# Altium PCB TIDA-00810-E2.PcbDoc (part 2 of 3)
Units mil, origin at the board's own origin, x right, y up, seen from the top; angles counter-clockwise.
Board outline 4527.56 x 3740.16 mil, 4 copper layers (Top Layer, Signal Layer 1, Signal Layer 2, Bottom Layer), stack 25.634 mil thick; 448 components, 198 nets, 1031 pads, 344 vias.
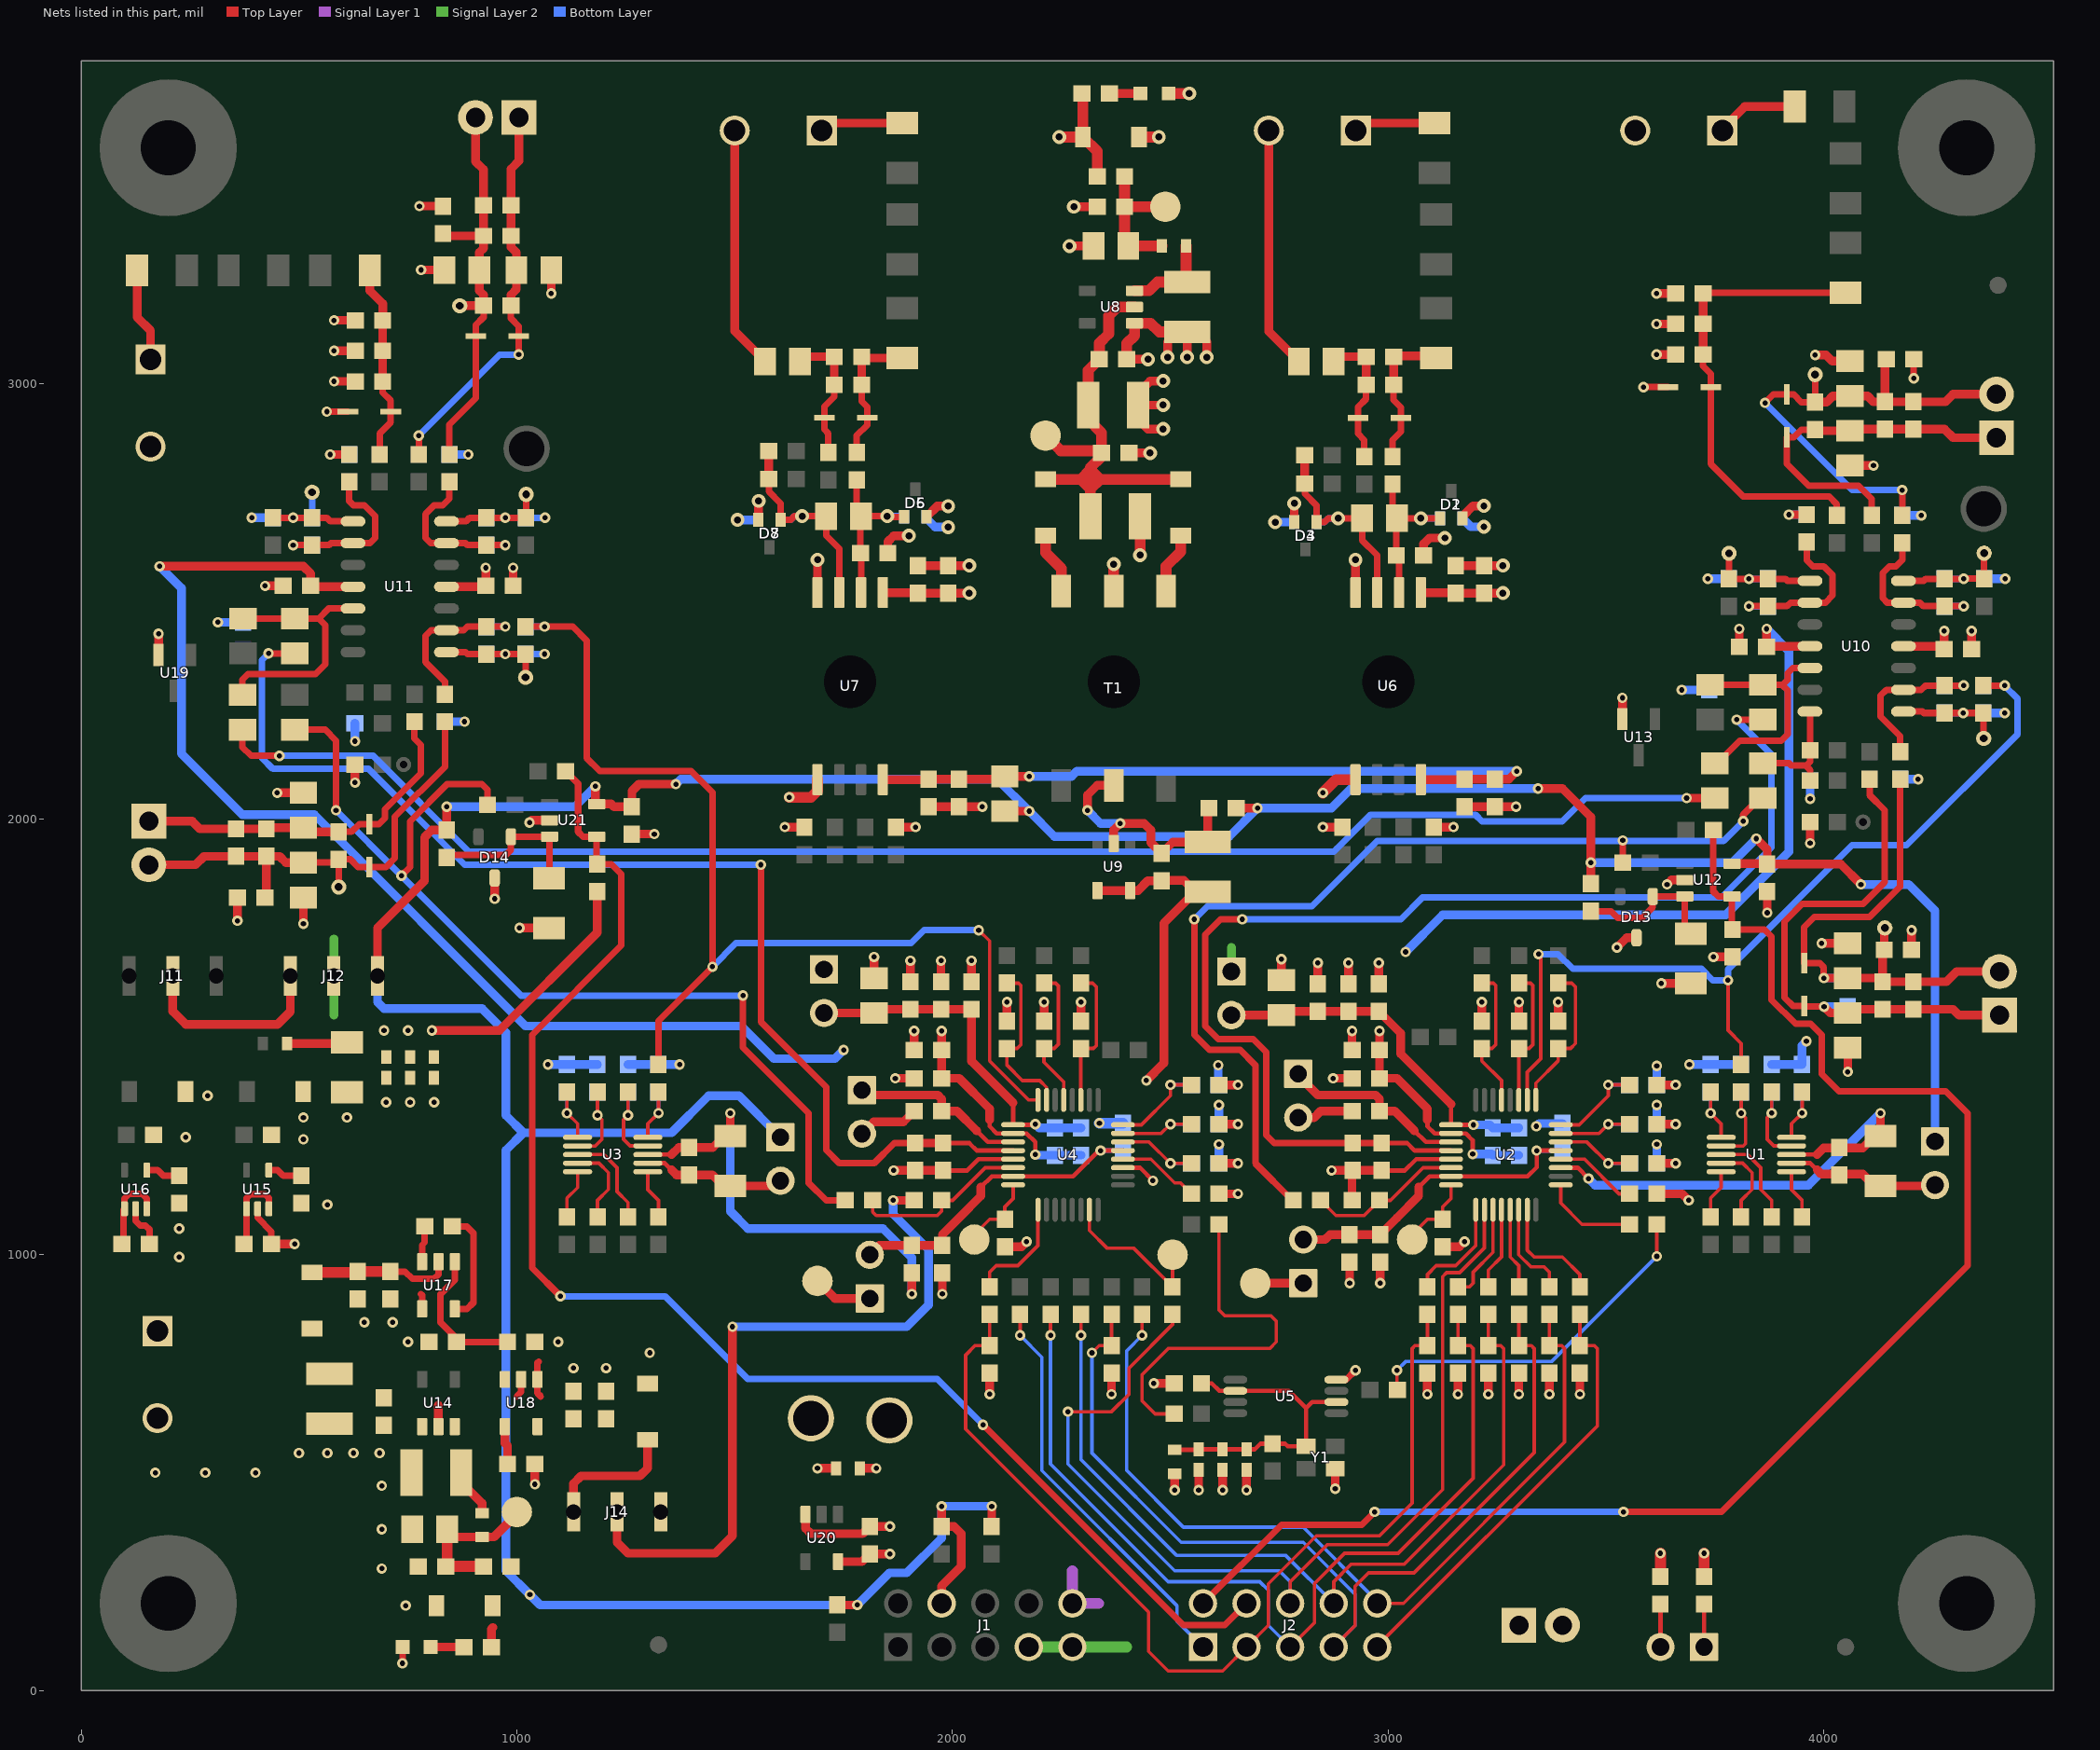
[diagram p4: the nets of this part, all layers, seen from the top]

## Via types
v1: diameter 24, hole 12, Top Layer to Bottom Layer, tented both sides, 309 vias
v2: diameter 32, hole 16, Top Layer to Bottom Layer, tented both sides, 35 vias

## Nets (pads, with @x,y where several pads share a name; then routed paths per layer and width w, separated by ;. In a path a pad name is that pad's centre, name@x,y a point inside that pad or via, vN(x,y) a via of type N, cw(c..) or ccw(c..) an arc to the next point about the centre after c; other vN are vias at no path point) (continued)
+5.0V_VDC: C35.1 C37.2 C40.1 C42.2 D1.2 D4.2 D5.2 D8.2 D10.1 R50.2 R65.2 R72.2 R73.2 U6.1 U7.1 | length 1014.1
  Top Layer w20: D8.2@1554.41,2686.5 1554.41,2729.41 v2(1555,2730) ; U7.1@1840,2519.57 1918.94,2519.57 C40.1@1920,2518.5 C42.2@1990,2518.5 v2(2038.5,2518.5) ; R65.2@1851.5,2610 1851.5,2636.5 1865,2650 v2(1900,2650) ; D5.2@1940.59,2693.5 1965,2717.91 v2(1990,2717.91) ; R73.2@2297.01,3665 R73.2@2299.04,3662.97 ; D4.2@2784.41,2681.5 v2(2784.41,2724.41) v2@2785,2725 ; U6.1@3075,2519.57 3153.94,2519.57 C37.2@3155,2518.5 C35.1@3220,2518.5 v2(3263.5,2518.5) ; R50.2@3081.5,2605 3081.5,2631.5 3095,2645 v2(3130,2645) ; D1.2@3170.27,2694.17 3194.68,2718.58 v2(3219.68,2718.58)
  Top Layer w25: v2(2245,3565) D10.1@2299.04,3565 ; R73.2@2299.04,3662.97 D10.1@2299.04,3565 ; R72.2@2332.01,3475 2332.01,3532.03 D10.1@2299.04,3565
+5V: C101.2 C115.2 D15.1 J1.4 J12.3 JP1.1 JP5.1 R122.2 R123.2 R134.2 R135.2 R140.2 R162.2 R163.2 R182.2 R183.2 U12.5 U21.5 | length 9121.8
  Top Layer w20: J12.3@680,1640 680,1750 788,1858 788,1958 804.54,1974.54 R123.2@839.13,1974.54 v1(839.13,2028.05) ; R135.2@941.5,100 941.5,141.5 945,145 ; v1(1180,2075) 1180,2037.72 U21.5@1183.27,2034.45 1216.73,2034.45 1222.64,2028.54 C115.2@1264.13,2028.54 1264.13,2064.13 1280,2080 v1(1365,2080) ; R140.2@1735,196.5 v1(1781.5,196.5) ; J1.4@1975,200 1975,240 2020,285 2020,360 2003.5,376.5 R163.2@1975,376.5 v1(1975,422.99) ; R162.2@2090,376.5 v1(2090,422.99) ; R183.2@2120,2018 v1(2176,2018) ; R182.2@2651.5,2025 v1(2700,2025) ; v1(3344,2070) 3400,2070 3465,2005 v1(3465,1900) R122.2@3465,1851.5 ; U12.5@3789.13,1897.4 3869.09,1897.4 C101.2@3870,1896.5 ; v1(3845,1955) 3870,1930 C101.2@3870,1896.5 ; v1(4085,1850) 4038.5,1896.5 C101.2@3870,1896.5
  Bottom Layer w20: J12.3@680,1640 680,1580 695,1565 920,1565 975,1510 975,1320 1015,1280 ; v1(839.13,2028.05) 1133.05,2028.05 v1(1180,2075) ; v1(1365,2080) 1376.5,2091.5 2102.5,2091.5 v1(2176,2018) 2234,1960 2635,1960 v1(2700,2025) 2870,2025 2915,2070 v1(3344,2070) ; JP5.1@1605,1270 1510,1365 1440,1365 1355,1280 1015,1280 ; v1(2090,422.99) v1(1975,422.99) 1975,350 1895,270 1855,270 v1(1781.5,196.5) 1053.5,196.5 v1(1030,220) 975,275 975,1240 1015,1280 ; v1(3465,1900) 3790,1900 v1(3845,1955) ; v1(4085,1850) 4195,1850 4255.13,1789.87 JP1.1@4255.13,1260
+6V_VDC: C50.1 C51.1 C52.2 C53.1 D9.1 D12.1 TP10.1 U8.2 | length 1150.1
  Top Layer w20: C52.2@2311.42,2917.09 C52.2@2311.42,2950 ; 2316.33,2801.47 2316.5,2801.47 ; 2316.42,2776.56 2316.5,2776.64 ; C51.1@2337.01,2845 C51.1@2342.01,2840
  Top Layer w25: D9.1@2213.5,2779.47 2313.5,2779.47 D12.1@2523.5,2779.47 ; TP10.1@2213.5,2880 2248.5,2845 C51.1@2337.01,2845 ; C52.2@2311.42,2917.09 2342.01,2886.5 C51.1@2342.01,2840 2342.01,2832.01 2316.5,2806.5 2316.5,2776.64 ; C52.2@2311.42,2950 2311.42,3029.41 C53.1@2337.01,3055 2337.01,3092.01 2358.5,3113.5 2358.5,3155 2378.5,3175 U8.2@2417.64,3175 ; 2316.33,2801.47 2294.33,2779.47 2316.42,2757.38 2338.5,2779.47 2316.5,2801.47 ; C50.1@2316.42,2695 2316.42,2776.56
-2P5V: C98.1 C99.1 D19.2 J14.1 U18.5 | length 315
  Top Layer w20: J14.1@1130,410 1130,475 1147.5,492.5 1282.5,492.5 1300,510 D19.2@1300,575.53
ADC1_CLKIN: R21.2 R47.1 | length 824
  Top Layer w8: v1(3020,735) 3020,691.5 R47.1@3021.5,690 ; v1(3616.56,996.56) R21.2@3616.56,1070
  Bottom Layer w8: v1(3020,735) 3040,755 3375,755 v1(3616.56,996.56)
ADC1_COMP: J2.2 R119.1 R124.1 U12.4 | length 3543.4
  Top Layer w15: J2.2@2575,200 2755,380 2939,380 v1@2968,409 ; v1(3540,410) 3765,410 4330,975 4330,1325 4280,1375 4035,1375 3995,1415 3995,1505 3970,1530 3935,1530 3880,1585 3880,1730 3863.5,1746.5 R124.1@3790,1746.5 3789.13,1747.36 U12.4@3789.13,1822.6 3757.4,1822.6 3746.5,1833.5 R119.1@3746.5,1975
  Bottom Layer w15: v1@2968,409 v1(2969,410) v1(3540,410)
ADC1_CS#: J2.9 R15.1 R164.1 | length 1008.9
  Top Layer w8: J2.9@2975,100 2975,102 3480,607 3480,785 3473.5,791.5 R164.1@3440,791.5 R164.1@3440,791.5 R15.1@3440.07,863.5
ADC1_REFOUT: C7.2 C8.2 R151.1 U2.12 | length 2772.8
  Top Layer w10: C8.2@2983.57,1256.49 3043.57,1256.49 3060.88,1239.19 U2.12@3144.08,1239.19
  Top Layer w15: v1(2665,1770) 2615,1770 2580,1735 2580,1525 2610,1495 2690,1495 2720,1465 2720,1275 2738.51,1256.49 C7.2@2918.57,1256.49 C8.2@2983.57,1256.49 ; v1(3800,2228.07) R151.1@3860,2228.07
  Bottom Layer w15: v1(2665,1770) 3029,1770 3079,1820 3765,1820 3880,1935 3880,2148.07 v1(3800,2228.07)
ADC1_SEL: JP9.1 R45.2 | length 98.5
  Top Layer w10: JP9.1@3725,100 R45.2@3725,198.5
ADC1_SPI_DONE: J2.6 R38.1 U2.18 | length 2360.4
  Top Layer w8: v1(2265,640) 2365,640 2405,680 2405,740 2505.07,840.07 R38.1@2505.07,863.5 ; J2.6@2775,200 2775,250 2860,335 2999,335 3125,461 3125,808 3125.07,950 3134.07,959 3164.07,959 3220.85,1015.79 U2.18@3220.85,1103.36
  Bottom Layer w8: v1(2265,640) 2265,520 2510,275 2750,275 2775,250 J2.6@2775,200
ADC2_CLKIN: R44.2 R48.1 | length 871.5
  Top Layer w8: R48.1@2508.5,635 2465,635 2435,665 2435,725 2495,785 2728,785 2743,800 2743,848 2731,860 2625,860 2611.56,873.44 R44.2@2611.56,1070
ADC2_COMP: J2.4 R120.2 R125.1 U21.4 | length 3316.6
  Top Layer w15: v1(1100,905) 1035,970 1035,1505 1240,1710 1240,1874 1217.46,1896.54 R125.1@1184.13,1896.54 1183.27,1897.41 U21.4@1183.27,1959.65 1151.54,1959.65 1140.63,1970.55 1140.63,2080.87 R120.2@1111.5,2110 ; v1(2070,610) 2530,150 2625,150 J2.4@2675,200
  Bottom Layer w15: v1(1100,905) 1340,905 1530,715 1965,715 v1(2070,610)
ADC2_REFOUT: C26.2 C27.2 R154.1 U4.12 | length 2737.8
  Top Layer w10: C27.2@1978.57,1256.49 2038.57,1256.49 2055.88,1239.19 U4.12@2139.08,1239.19
  Top Layer w15: v1(430,2380) R154.1@490,2380 ; v1(1560,1895) 1560,1535 1710,1385 1710,1240 1740,1210 1820,1210 1866.5,1256.49 C26.2@1913.57,1256.49
  Top Layer w20: C26.2@1913.57,1256.49 C27.2@1978.57,1256.49
  Bottom Layer w15: v1(430,2380) 415,2365 415,2140 440,2115 660,2115 880,1895 v1(1560,1895)
ADC2_SEL: JP9.2 R46.2 | length 98.5
  Top Layer w10: JP9.2@3625,100 R46.2@3625,198.5
ADC2_SPI_DONE: J2.1 R43.1 | length 937.5
  Top Layer w8: v1(2155,815) v1(2155,815) R43.1@2155.07,863.5
  Bottom Layer w8: v1(2155,815) 2205,765 2205,505 2515,195 2515,160 J2.1@2575,100
ADC_RESET: J2.3 R12.1 R14.1 R35.1 R37.1 | length 2293.4
  Top Layer w8: R37.1@2085.07,863.5 R35.1@2085,791.5 R35.1@2085,791.5 2051.5,791.5 2030,770 2030,600 2450,180 2450,90 2495,45 2620,45 J2.3@2675,100 2725,150 2725,245 2835,355 2980,355 3055,430 3055,785 3061.5,791.5 R12.1@3090,791.5 R12.1@3090,791.5 R14.1@3090.07,863.5
ADC_SPI_DRDY: J2.5 R19.1 R42.1 R167.1 | length 2155.2
  Top Layer w8: v1(2225,815) R42.1@2225.07,863.5 ; J2.5@2775,100 2830.65,155.65 2830.65,245.65 2900,315 3023,315 3195,487 3195,785 3188.5,791.5 R167.1@3160,791.5 R167.1@3160,791.5 R19.1@3160.07,863.5
  Bottom Layer w8: v1(2225,815) 2225,520 2495,250 2705.32,250 2725,230.32 2725,150 J2.5@2775,100
ADC_SPI_MISO: J2.7 R13.1 R18.1 R36.1 R41.1 | length 2279.6
  Top Layer w8: v1(2320,775) 2336.5,791.5 R36.1@2365,791.5 R36.1@2365,791.5 R41.1@2365.07,863.5 ; J2.7@2875,100 2924,149 2924,239 2955,270 3059,270 3335,546 3335,785 3328.5,791.5 R13.1@3300,791.5 R13.1@3300,791.5 R18.1@3300.07,863.5
  Bottom Layer w8: v1(2320,775) 2320,545 2525,340 2805,340 2924,221 2924,149 J2.7@2875,100
ADC_SPI_MOSI: J2.8 R17.1 R40.1 R165.1 | length 1977.9
  Top Layer w8: v1(2295,815) R40.1@2295.07,863.5 ; J2.8@2875,200 2875,250 2915,290 3037,290 3265,518 3265,785 3258.5,791.5 R165.1@3230,791.5 R165.1@3230,791.5 R17.1@3230.07,863.5
  Bottom Layer w8: v1(2295,815) 2295,530 2515,310 2765,310 J2.8@2875,200
ADC_SPI_SCLK: J2.10 R16.1 R39.1 R166.1 | length 1985.2
  Top Layer w8: v1(2435,815) R39.1@2435.07,863.5 ; J2.10@2975,200 3035,200 3405,570 3405,785 3398.5,791.5 R166.1@3370,791.5 R166.1@3370,791.5 R16.1@3370.07,863.5
  Bottom Layer w8: v1(2435,815) 2400,780 2400,505 2530,375 2805,375 2975,205 J2.10@2975,200
AGND: C3.2 C4.2 C9.2 C10.2 C11.2 C12.2 C15.2 C20.2 C21.2 C22.2 C23.2 C24.2 C25.2 C30.2 C36.1 C38.2 C41.1 C43.2 C56.1 C57.2 C58.2 C59.1 C60.1 C61.1 C64.1 C67.2 C68.2 C69.1 C74.2 C75.2 C76.1 C77.1 C78.1 C79.2 C80.1 C81.2 C82.2 C83.2 C84.2 C85.1 C86.2 C87.2 C88.2 C89.2 C90.2 C91.2 C92.2 C94.2 C95.2 C96.2 C97.2 C98.2 C99.2 C100.2 C101.1 C102.2 C103.2 C104.2 C107.2 C108.2 C109.2 C110.2 C111.2 C112.2 C113.2 C115.1 C122.2 C123.2 C124.1 C125.1 C126.2 C127.2 C128.1 C129.1 C130.2 C131.2 C132.2 C133.2 C134.2 C135.2 C136.2 C137.2 D13.3 D14.3 D15.2 D16.1 D17.2 D18.2 D19.1 D23.2 D24.2 J5.2 J6.2 J13.2 J14.3 L1.1 R9.1 R10.1 R11.1 R32.1 R33.1 R34.1 R45.1 R46.1 R79.2 R82.2 R88.1 R89.1 R90.1 R91.1 R118.2 R121.2 R132.1 R133.1 R141.2 R142.2 R170.2 R171.2 R174.1 R175.1 R176.1 R177.1 R178.1 R179.1 TP5.1 U6.5 U7.5 U12.2 U13.2 U14.1 U15.2 U16.2 U17.4 U18.1 U19.2 U21.2 | length 5444.6
  Top Layer w15: U16.2@125,1105.71 125,1078 135.5,1067.5 147.5,1067.5 156.5,1058.5 C90.2@156.5,1025 ; U15.2@405,1105.71 405,1085 436.5,1053.5 C87.2@436.5,1025 ; v1(563.63,2934.86) D24.2@612.13,2934.86 ; v1(737.52,62.52) D16.1@737.52,100 ; 780,910 782.6,907.4 U17.4@782.6,875.87 ; 1050,755 1047.4,752.4 U18.1@1047.4,714.13 1047.4,682.6 1055,675 ; v1(3586.07,2991.07) D23.2@3641.97,2991.07 ; v1(4206.5,3011.5) R170.2@4206.5,3055
  Top Layer w20: U19.2@177.6,2376.34 v1(177.6,2425) ; v1(358.5,1766.5) R142.2@358.5,1820 ; v1(422.01,2535) C69.1@463.5,2535 ; C87.2@436.5,1025 v1(490,1025) ; v1(450,2060) C125.1@510,2060 ; v1(510,1760) C123.2@510,1820 ; v1(571.5,2836.5) R82.2@615,2836.5 ; v1(580.37,3004.39) C61.1@628.88,3004.39 ; v1(580.37,3074.39) R91.1@628.88,3074.39 ; v1(580.37,3144.39) R90.1@628.88,3144.39 ; v1(628.5,2083.5) R121.2@628.5,2125 ; v1(776.5,3406.5) R171.2@830,3406.5 ; v1(780,3260) C127.2@834,3260 ; v1(949.13,1817.05) D14.3@949.13,1864.8 ; C64.1@991.5,2535 v1(991.5,2576.5) ; v1(1006.22,1749.96) R133.1@1074.13,1749.96 ; v1(1029.13,1992.05) 1034.13,1997.05 U21.2@1075,1997.05 ; v1(1041.5,473.5) C100.2@1041.5,520 ; v1(1079,3206) C129.1@1079,3260 ; C115.1@1264.13,1965.55 v1(1315.63,1965.55) ; v1(1615,1981.5) C112.2@1660,1981.5 ; v1(1690,510) L1.1@1732.44,510 ; C21.2@1820.07,1635 v1(1820.07,1683.5) ; v1(1868.57,1405) C24.2@1912.07,1405 ; C113.2@1870,1981.5 v1(1915,1981.5) ; C23.2@1903.57,1626.49 v1(1903.57,1675) ; C25.2@1912.07,1470 v1(1912.07,1513.5) ; C41.1@1945,2028.5 C43.2@2015,2028.5 v1(2068.5,2028.5) ; C20.2@1973.57,1626.49 v1(1973.57,1675) ; C22.2@2043.57,1626.49 v1(2043.57,1675) ; C109.2@2125.07,1536.49 v1(2125.07,1580) ; C108.2@2210.07,1536.49 v1(2210.07,1580) ; C107.2@2295.07,1536.49 v1(2295.07,1580) ; C30.2@2611.56,1140 v1(2655.07,1140) ; C4.2@2755.07,1630 v1(2755.07,1678.5) ; C10.2@2838.57,1621.49 v1(2838.57,1670) ; v1(2850,1981.5) C110.2@2895,1981.5 ; v1(2873.57,1405) C11.2@2917.07,1405 ; C3.2@2908.57,1621.49 v1(2908.57,1670) ; C12.2@2917.07,1470 v1(2917.07,1513.5) ; C9.2@2978.57,1621.49 v1(2978.57,1670) ; C111.2@3105,1981.5 v1(3150,1981.5) ; C38.2@3175,2028.5 C36.1@3245,2028.5 v1(3293.5,2028.5) ; C104.2@3215.07,1536.49 v1(3215.07,1580) ; C103.2@3300.07,1536.49 v1(3300.07,1580) ; C102.2@3390.07,1536.49 v1(3390.07,1580) ; v1(3525,1705) 3547.76,1727.76 D13.3@3570,1727.76 ; U13.2@3537.6,2229.41 v1(3537.6,2278.07) ; v1(3616.07,3066.07) C60.1@3659.69,3066.07 ; v1(3616.07,3136.07) R89.1@3659.69,3136.07 ; v1(3616.07,3206.07) R88.1@3659.69,3206.07 ; C15.2@3616.56,1140 3675,1140 v1(3690,1125) ; v1(3627.09,1622.91) R132.1@3695,1622.91 ; v1(3640,1850) 3650,1860 U12.2@3680.87,1860 ; C59.1@3805.8,2394.78 v1(3805.8,2436.28) ; v1(3870,1785) C101.1@3870,1833.5 ; v1(3920,2698.5) R79.2@3961,2698.5 ; v1(3968.5,1944.57) R118.2@3968.5,1993.07 ; v1(3980,3065) 4005,3065 4019,3051 C126.2@4060,3051 ; v1(3995,1715) C122.2@4055,1715 ; v1(4055,1420) C124.1@4055,1475 ; C128.1@4060,2811 v1(4114,2811) ; R141.2@4201.5,1700 v1(4201.5,1745) ; C56.1@4339.36,2390 v1(4339.36,2431.5)
  Top Layer w25: v1(1625,2050) 1675,2050 1690,2065 U7.5@1690,2090.43 ; v1(2850,2060) 2880.43,2090.43 U6.5@2925,2090.43 ; R46.1@3625,261.5 v1(3625,315) ; R45.1@3725,261.5 v1(3725,315)
  Bottom Layer w15: C68.2@1020,2378.5 v1(1063.5,2378.5) ; C75.2@1021.32,2691.5 v1(1064.82,2691.5)
  Bottom Layer w20: v1(391.5,2691.5) C58.2@440,2691.5 ; v1(571.5,2836.5) R179.1@615,2836.5 ; v1(628.5,2178.5) C77.1@628.5,2220 ; R175.1@835,2223.5 v1(880,2223.5) ; R177.1@845,2836.5 v1(888.5,2836.5) ; v1(1071.5,1436.5) C136.2@1115,1436.5 C137.2@1185,1436.5 ; C134.2@1255,1436.5 C135.2@1325,1436.5 v1(1373.5,1436.5) ; v1(2610,1435) 2610,1391.56 R34.1@2611.56,1390 ; R32.1@2611.56,1210 v1(2611.56,1253.5) ; R33.1@2611.56,1300 v1(2611.56,1343.5) ; R9.1@3616.56,1210 v1(3616.56,1253.5) ; R10.1@3616.56,1300 v1(3616.56,1343.5) ; R11.1@3616.56,1390 v1(3616.56,1433.5) ; v1(3691.5,1436.5) C132.2@3740,1436.5 C133.2@3810,1436.5 ; v1(3733.8,2551.28) C57.2@3782.3,2551.28 ; C130.2@3880,1436.5 C131.2@3950,1436.5 3950,1480 v1(3960,1490) ; v1(3920,2698.5) R178.1@3961,2698.5 ; v1(3968.5,2046.58) C76.1@3968.5,2088.07 ; R174.1@4175,2091.58 v1(4216.5,2091.58) ; R176.1@4180,2696.5 v1(4223.5,2696.5) ; C67.2@4366.41,2243.29 v1(4414.91,2243.29) ; C74.2@4367.87,2551.5 v1(4416.37,2551.5)
  other v1: 745,195 690,280 690,370 690,470 170,500 285,500 400,500 500,545 565,545 625,545 685,545 1130,740 1205,740 1305,775 750,800 1095,800 650,845 715,845 225,995 225,1060 565,1115 510,1265 240,1270 510,1315 610,1315 700,1350 755,1350 810,1350 290,1365
AVCC_3.3: C81.1 C82.1 C83.1 C84.1 C114.1 J1.7 J1.9 J15.1 JP3.1 JP7.1 L2.1 L5.2 R5.2 R6.2 R7.2 R8.1 R12.2 R13.2 R28.2 R29.2 R30.2 R31.1 R35.2 R36.2 R124.2 R125.2 R164.2 R165.2 R166.2 R167.2 TP1.1 TP6.1 U20.5 | length 2142.3
  Top Layer w20: L5.2@472.56,1485 607.91,1485 C81.1@610,1487.09 ; v1(805,1515) 960,1515 1184.13,1739.13 R125.2@1184.13,1833.55 ; TP6.1@1690,940 1730,900 JP7.1@1810,900 ; U20.5@1737.4,295.87 1792.36,295.87 C114.1@1810,313.5 v1(1856.5,313.5) ; v1(2085,680) R35.2@2085,728.5 ; R31.1@2120.07,1018.5 2158.57,1018.5 v1(2170.07,1030) ; v1(2365,680) R36.2@2365,728.5 ; v1(2510,460) L2.1@2510,497.44 ; R28.2@2611.56,1210 v1(2655.07,1210) ; R29.2@2611.56,1300 v1(2655.07,1300) ; R30.2@2611.56,1390 v1(2655.07,1390) ; TP1.1@2695,935 JP3.1@2805.07,935 ; v1(3090,680) R12.2@3090,728.5 ; R8.1@3125.07,1018.5 3163.57,1018.5 v1(3175.07,1030) ; v1(3160,680) R167.2@3160,728.5 ; v1(3230,680) R165.2@3230,728.5 ; v1(3300,680) R13.2@3300,728.5 ; v1(3370,680) R166.2@3370,728.5 ; v1(3440,680) R164.2@3440,728.5 ; R5.2@3616.56,1210 v1(3660.07,1210) ; R6.2@3616.56,1300 v1(3660.07,1300) ; R7.2@3616.56,1390 v1(3660.07,1390) ; v1(3746.5,1683.5) R124.2@3790,1683.5
  Signal Layer 2 w25: J1.7@2175,100 J1.9@2275,100 2400,100
  other v1: 695,1515 750,1515
AVDD: C56.2 C64.2 J12.2 JP2.1 JP6.1 R152.2 R155.2 U10.4 U11.4 | length 621.8
  Top Layer w20: U11.4@838.45,2533.03 926.53,2533.03 C64.2@928.5,2535 v1(928.5,2576.5) ; U10.4@4182.75,2396.56 4269.81,2396.56 C56.2@4276.37,2390 v1(4276.37,2431.5)
  Signal Layer 2 w20: 580,1550 J12.2@580,1640 580,1725 ; 2640,1705 2640.07,1704.93 JP2.1@2640.07,1650
  Bottom Layer w20: v1(313.5,2451.5) R155.2@371.46,2451.5 ; v1(3673.72,2296.28) R152.2@3737.3,2296.28
AVDD_J1: C3.1 C4.1 C9.1 C10.1 C118.1 C119.1 JP2.2 U2.9 | length 829.6
  Top Layer w10: 3144.08,1345.98 U2.9@3144.08,1298.24 v1(3195.76,1298.24)
  Top Layer w20: JP2.2@2640.07,1550 C4.1@2755.07,1550 2763.57,1558.5 C10.1@2838.57,1558.5 C3.1@2908.57,1558.5 C9.1@2978.57,1558.5 3028.57,1508.5 3028.57,1461.5 3144.08,1345.98
  Bottom Layer w20: v1(3195.76,1298.24) 3233.26,1298.24 C118.1@3240,1291.5 C119.1@3300,1291.5
AVDD_J2: C20.1 C21.1 C22.1 C23.1 C120.1 C121.1 JP6.2 U4.9 | length 807
  Top Layer w10: 2139.08,1349.02 U4.9@2139.08,1298.24 2188.24,1298.24 v1(2190,1300)
  Top Layer w20: JP6.2@1705.07,1555 C21.1@1820.07,1555 1828.57,1563.5 C23.1@1903.57,1563.5 C20.1@1973.57,1563.5 C22.1@2043.57,1563.5 2043.57,1444.53 2139.08,1349.02
  Bottom Layer w20: v1(2190,1300) 2198.5,1291.5 C120.1@2235,1291.5 C121.1@2295,1291.5
AVSS: C7.1 C8.1 C11.1 C12.1 C13.2 C14.2 C24.1 C25.1 C26.1 C27.1 C28.2 C29.2 C59.2 C69.2 C118.2 C119.2 C120.2 C121.2 J14.2 JP4.2 JP8.2 U2.10 U2.13 U4.10 U4.13 U10.11 U11.11 | length 8037.1
  Top Layer w10: C27.1@1978.57,1193.5 2033.57,1193.5 2059.57,1219.5 U4.13@2139.08,1219.5 ; 2085.07,1310 2085.07,1295 2101.51,1278.56 U4.10@2139.08,1278.56 2170.13,1278.56 2190,1258.68 v1(2190,1230) ; C8.1@2983.57,1193.5 3038.57,1193.5 3064.57,1219.5 U2.13@3144.08,1219.5 ; 3090.07,1310 3090.07,1295 3106.51,1278.56 U2.10@3144.08,1278.56 3178.24,1278.56 3194,1262.8 v1(3194,1231)
  Top Layer w20: v1(180,2580) 510,2580 526.5,2563.5 C69.2@526.5,2535 528.47,2533.03 U11.11@623.88,2533.03 ; J14.2@1230,410 1230,340 1255,315 1455,315 1495,355 v1(1495,835) ; JP8.2@1792,1278 1819,1305 1887.07,1305 C28.2@1912.07,1330 ; v1(1863.57,1125) C29.2@1912.07,1125 ; v1(1865.06,1193.5) C26.1@1913.57,1193.5 C27.1@1978.57,1193.5 ; v1(1975.06,1513.5) C25.1@1975.06,1470 C24.1@1975.06,1405 2015.07,1405 2085.07,1335 2085.07,1310 ; JP4.2@2793.57,1311.5 2790.07,1315 2830.07,1315 2845.07,1330 C13.2@2917.07,1330 ; v1(2870.06,1193.5) C7.1@2918.57,1193.5 ; C14.2@2917.07,1125 2917.07,1192.01 C7.1@2918.57,1193.5 ; v1(2980.06,1513.5) C12.1@2980.06,1470 C11.1@2980.06,1405 3020.07,1405 3090.07,1335 3090.07,1310 ; C8.1@2983.57,1193.5 C7.1@2918.57,1193.5 ; v1(3868.8,2436.28) C59.2@3868.8,2394.78 3870.57,2396.56 U10.11@3968.18,2396.56
  Bottom Layer w20: v1(180,2580) 230,2530 230,2150 370,2010 535,2010 1020,1525 1515,1525 1590,1450 1730,1450 v1(1750,1470) ; v1(1495,835) 1895,835 1945,885 1945,1012 1863.57,1093.43 v1(1863.57,1125) ; v1(2190,1230) 2191.5,1228.5 C120.2@2235,1228.5 C121.2@2295,1228.5 ; v1(3040,1695) 3125,1780 3775,1780 3920,1925 3920,2385.08 v1(3868.8,2436.28) ; v1(3194,1231) 3237.5,1231 C118.2@3240,1228.5 C119.2@3300,1228.5
CT_1_OUT: C67.1 R96.2 R143.2 U2.2 | length 2149.7
  Top Layer w8: U2.2@3319.28,1355.33 3319.28,1419.21 3350,1449.93 3350,1685 v1(3345,1690) ; v1(3780,1630) 3780,1515.13 3810.13,1485 R143.2@3810.13,1436.49
  Top Layer w15: R96.2@4366.41,2306.28 v1(4414.92,2306.28)
  Bottom Layer w15: v1(3345,1690) 3390,1690 3423.87,1656.13 3718.87,1656.13 3745,1630 v1(3780,1630) 3780,1655 4065,1940 4190,1940 4445,2195 4445,2276.19 v1(4414.92,2306.28) C67.1@4366.41,2306.28
CT_2_OUT: C68.1 R97.2 R149.2 U4.8 | length 2568.6
  Top Layer w8: v1(2060,1745) 2085,1720 2085,1445 2174.67,1355.33 U4.8@2196.17,1355.33
  Top Layer w15: R97.2@1020,2441.5 v1(1063.5,2441.5) 1128.5,2441.5 1160,2410 1160,2140 1190,2110 1400,2110 1449,2061 v1(1449,1661) 1325.07,1537.07 R149.2@1325.07,1436.49
  Bottom Layer w15: C68.1@1020,2441.5 v1(1063.5,2441.5) ; v1(1449,1661) 1503,1715 1905,1715 1935,1745 v1(2060,1745)
DC_IN: C85.2 C86.1 C87.1 C90.1 D20.2 J13.1 U14.2 U15.1 U15.3 U16.1 U16.3 | length 430.5
  Top Layer w15: C90.1@93.5,1025 97,1028.5 97,1103.3 U16.1@99.41,1105.71 99.41,1129.41 110,1140 140,1140 150.59,1129.41 U16.3@150.59,1105.71 ; C87.1@373.5,1025 379.41,1030.91 U15.1@379.41,1105.71 379.41,1130.41 388,1139 422,1139 430.59,1130.41 U15.3@430.59,1105.71
  Top Layer w20: U14.2@820,605.87 820,655
EXT_REF1: R20.1 R127.1 R157.1 | length 2261.2
  Top Layer w15: v1(2555,1770) 2555,1505 2590,1470 2660,1470 2695,1435 2695,1210 2780,1125 R157.1@2782.07,1125 ; R127.1@3538.5,1900 v1(3538.5,1951) ; v1(3815,1995) 3815,2010 3853.07,2048.07 R20.1@3860,2048.07
  Bottom Layer w15: v1(2555,1770) 2585,1800 2825,1800 2975,1950 3770,1950 v1(3815,1995)
EXT_REF2: R128.1 R139.1 R161.1 | length 2354.8
  Top Layer w15: R139.1@490,2205 560,2205 585,2180 v1(585,2020) ; v1(735,1870) 755,1890 755,1995 840,2080 920,2080 932.64,2067.36 R128.1@932.64,2032.05 ; v1(1519,1595) 1519,1476 1670,1325 1670,1165 1710,1125 R161.1@1753.57,1125
  Bottom Layer w15: v1(585,2020) v1(735,1870) 1010,1595 v1(1519,1595)
GND: C1.2 C2.2 C5.2 C6.2 C16.2 C17.2 C18.2 C19.2 C31.2 C32.2 C33.2 C34.2 C45.1 C46.1 C114.2 C116.2 C117.2 J1.10 J15.2 L1.2 TP3.1 U1.3 U2.27 U3.3 U4.27 U5.4 U9.4 U9.5 U20.3 Y1.2 | length 3956.6
  Top Layer w10: U3.3@1300.77,1230 1355.07,1230 ; U4.27@2391.05,1199.82 2430.19,1199.82 v1(2460,1170) ; U2.27@3396.05,1199.82 3435.19,1199.82 v1(3460,1175) ; U1.3@3930.13,1230 3984.42,1230
  Top Layer w15: U5.4@2903.39,713.39 v1(2925,735)
  Top Layer w20: 1355.07,1230 1371.56,1246.49 C16.2@1395.07,1246.49 1449.56,1246.49 1475.15,1272.09 C17.2@1490.07,1272.09 1490.07,1324.93 v1(1490,1325) ; U20.3@1662.6,404.13 1662.6,372.4 1675,360 1793.5,360 C114.2@1810,376.5 v1(1856.5,376.5) ; L1.2@1787.56,510 v1(1825,510) ; v1(1906.57,910) C19.2@1906.57,958.5 ; v1(1976.57,910) C18.2@1976.57,958.5 ; U9.4@2332.6,1835.87 U9.5@2407.4,1835.87 2425.87,1835.87 2448.5,1858.5 C46.1@2480,1858.5 2480.77,1859.27 2530.73,1859.27 C45.1@2557.09,1832.91 ; v1(2445,1400) 2485,1440 2485,1760.83 C45.1@2557.09,1832.91 ; v1(2462.13,705) C31.2@2508.5,705 ; v1(2565,460) C32.2@2565,506.38 ; C45.1@2578.09,1825 C45.1@2586,1832.91 C45.1@2557.09,1832.91 ; v1(2620,460) C33.2@2620,506.38 ; v1(2675,460) C34.2@2675,506.38 ; v1(2878.46,463.03) Y1.2@2878.46,509.41 ; v1(2911.57,935) C5.2@2911.57,983.5 ; v1(2981.57,935) C6.2@2981.57,983.5 ; 3984.42,1230 3999.42,1245 C1.2@4027.93,1245 ; C1.2@4034.42,1251.49 C1.2@4027.93,1245 ; C2.2@4129.42,1272.08 4116.51,1272.08 4089.42,1245 4036.63,1245 C1.2@4035.13,1246.49 4033.64,1245 C1.2@4027.93,1245 ; v1(4130,1325) 4130.13,1324.87 C2.2@4130.13,1272.08
  Signal Layer 1 w25: 2275,275 J1.10@2275,200 2335,200
  Bottom Layer w20: v1(1490,1325) 1490,1100 1530,1060 1840,1060 1906.57,993.43 v1(1906.57,910) ; v1(3340,1295) 3346.5,1301.5 C116.2@3400,1301.5 ; v1(3460,1175) 3475,1160 3965,1160 v1(4130,1325)
  Bottom Layer w25: v1(2337.18,1302.18) C117.2@2391.05,1302.18
GND_VDC: C35.2 C37.1 C40.2 C42.1 C47.1 C48.2 C49.1 C50.2 C51.2 C52.1 C53.2 D2.1 D3.1 D6.1 D7.1 D10.2 D11.1 J3.2 J4.2 R59.1 R70.1 T1.5 U6.4 U7.4 U8.1 | length 2850.4
  Top Layer w20: J4.2@1500,3580 1500,3120 R70.1@1570,3050 ; R70.1@1565,3045 R70.1@1570,3040 ; U7.4@1690,2519.57 v2(1690,2595) ; C40.2@1920,2581.5 C42.1@1990,2581.5 v2(2038.5,2581.5) ; v2(2268.5,3315) C47.1@2323.5,3315 ; v2(2278.5,3405) C48.2@2332.01,3405 ; C53.2@2400,3055 v2(2448.5,3055) ; C51.2@2405,2840 v2(2453.5,2840) ; 2448.77,2894.73 2448.5,2895 ; v2(2483.5,2895) 2448.5,2895 ; v2(2483.5,2950) C52.1@2425.59,2950 ; v2(2483.5,3005) 2453.5,3005 2425.59,2977.09 C52.1@2425.59,2950 ; v2(2493.5,3060) 2493.5,3095 2503.5,3105 2503.5,3117.91 C49.1@2538.5,3117.91 ; v2(2538.5,3060) C49.1@2538.5,3117.91 ; v2(2583.5,3060) 2583.5,3095 2560.59,3117.91 C49.1@2538.5,3117.91 ; J3.2@2725.96,3580 2725.96,3119.03 R59.1@2795,3050 ; U6.4@2925,2519.57 v2(2925,2595) ; C37.1@3155,2581.5 3230,2581.5 v2(3263.5,2581.49) ; C52.1@2425.59,2950 2425.59,2917.91 2448.5,2895
  Top Layer w25: T1.5@2370,2522.64 v2(2370,2585) ; C53.2@2400,3055 2400,3091.5 2417.64,3109.13 U8.1@2417.64,3137.6 2454.69,3137.6 2474.37,3117.91 C49.1@2503.5,3117.91 ; D10.2@2427.97,3565 v2(2473.5,3565) ; v2(2430.59,2605.59) C50.2@2430.59,2695 ; D11.1@2495.98,3665 v2(2543.5,3665)
  Bottom Layer w20: v2(1506.5,2686.5) D7.1@1554.41,2686.5 ; D6.1@1940.59,2693.5 1940.59,2689.41 1960,2670 v2(1990,2670) ; v2(2740.91,2680.9) 2741.5,2681.5 D3.1@2784.41,2681.5 ; D2.1@3170.27,2694.17 D2.1@3170.27,2690.08 3189.68,2670.67 v2(3219.68,2670.67)
NetC1_1: C1.1 C2.1 JP1.2 U1.2 | length 353.1
  Top Layer w10: U1.2@3930.13,1210.31 3969.11,1210.31 3984.42,1195
  Top Layer w20: 3984.42,1195 3994.42,1185 C1.1@4030.92,1185 ; C1.1@4034.42,1188.5 C1.1@4030.92,1185 ; JP1.2@4254.42,1160 4252.34,1157.91 4116.51,1157.91 4089.42,1185 4036.63,1185 C1.1@4035.13,1183.5 4033.64,1185 C1.1@4030.92,1185
NetC5_1: C5.1 C6.1 C116.1 JP3.2 U2.15 U2.29 | length 769.2
  Top Layer w10: 3070.07,1155 3095.07,1180 3143.95,1180 U2.15@3144.08,1180.13 3320.13,1180.13 3340.81,1200.81 v1(3340.81,1239.19) U2.29@3396.05,1239.19
  Top Layer w20: JP3.2@2805.07,1035 2855.07,1035 2866.56,1046.5 C5.1@2911.57,1046.5 C6.1@2981.57,1046.5 3020.07,1085 3070.07,1135 3070.07,1155
  Bottom Layer w10: v1(3340.81,1239.19) 3341.5,1238.5 C116.1@3400,1238.5
NetC13_1: C13.1 JP4.1 U2.11 | length 434.8
  Top Layer w10: 3060.07,1285 3086.19,1258.87 U2.11@3144.08,1258.87
  Top Layer w20: JP4.1@2790.07,1415 2838.49,1366.57 2970.99,1366.57 2980.06,1357.5 C13.1@2980.06,1330 3015.07,1330 3060.07,1285
NetC14_1: C14.1 R157.2 U2.14 | length 359
  Top Layer w8: R157.2@2845.06,1125 2880.06,1090 2945.06,1090 C14.1@2980.06,1125 3005.07,1125 3079.88,1199.82 U2.14@3144.08,1199.82
NetC15_1: C15.1 U2.28 | length 190.4
  Top Layer w8: U2.28@3396.05,1219.5 3450.5,1219.5 3530,1140 C15.1@3553.57,1140
NetC16_1: C16.1 C17.1 JP5.2 U3.2 | length 330.9
  Top Layer w10: U3.2@1300.77,1210.31 1339.75,1210.31 1355.07,1195
  Top Layer w20: 1355.07,1195 1366.56,1183.5 C16.1@1395.07,1183.5 1448.57,1183.5 1474.16,1157.91 C17.1@1490.07,1157.91 1592.91,1157.91 JP5.2@1605,1170
NetC18_1: C18.1 C19.1 C117.1 JP7.2 U4.15 U4.29 | length 731.4
  Top Layer w10: 2065.07,1155 2090.2,1180.13 U4.15@2139.08,1180.13 ; U4.15@2139.08,1180 2276.63,1180 2335.81,1239.19 v1(2340,1239.19) U4.29@2391.05,1239.19
  Top Layer w20: JP7.2@1831.5,1021.5 C19.1@1906.57,1021.5 C18.1@1976.57,1021.5 1976.57,1046.5 2015.07,1085 2065.07,1135 2065.07,1155
  Bottom Layer w10: v1@2335.81,1239.19 v1(2340,1239.19) C117.1@2391.05,1239.19
NetC28_1: C28.1 JP8.1 U4.11 | length 423.2
  Top Layer w10: 2055.07,1285 2081.19,1258.87 U4.11@2139.08,1258.87
  Top Layer w20: JP8.1@1785,1375 1785,1366.57 1965.99,1366.57 1975.06,1357.5 C28.1@1975.06,1330 2010.07,1330 2055.07,1285
NetC29_1: C29.1 R161.2 U4.14 | length 412.7
  Top Layer w8: R161.2@1816.56,1125 1816.56,1098.44 1825,1090 1965,1090 1975.06,1100.06 C29.1@1975.06,1125 2000.07,1125 2074.88,1199.82 U4.14@2139.08,1199.82
NetC30_1: C30.1 U4.28 | length 190.4
  Top Layer w8: U4.28@2391.05,1219.5 2455.57,1219.5 2510.07,1165 2523.57,1165 C30.1@2548.57,1140
NetC31_1: C31.1 C32.1 C33.1 C34.1 L2.2 R49.1 U5.2 U5.6 Y1.4 | length 736.4
  Top Layer w10: L2.2@2510,552.56 C32.1@2563.94,552.56 ; C32.1@2565,553.62 C33.1@2620,553.62 C34.1@2675,553.62 2694.12,553.62 2707,566.5 R49.1@2735,566.5 2763.5,566.5 2769.41,560.59 Y1.4@2811.54,560.59 2811.54,648.54 ; C31.1@2571.5,705 2595,705 2612.2,687.8 U5.6@2648.86,687.8 2772.28,687.8 2811.54,648.54 ; U5.2@2881.14,662.2 2825.2,662.2 2811.54,648.54
  Top Layer w15: C32.1@2563.94,552.56 C32.1@2565,553.62
NetC36_2: C36.2 C38.1 C41.2 C43.1 R183.1 U6.8 U7.8 | length 1690.8
  Top Layer w20: U7.8@1840,2090.43 1943.94,2090.43 C41.2@1945,2091.5 C43.1@2015,2091.5 2113.5,2091.5 R183.1@2120,2098 v1(2176,2098) ; U6.8@3075,2090.43 3173.94,2090.43 C38.1@3175,2091.5 C36.2@3245,2091.5 3277,2091.5 v1(3295,2109.5)
  Bottom Layer w20: v1(2176,2098) 2273.5,2098 2285,2109.5 v1(3295,2109.5)
NetC39_1: C39.1 D1.1 D2.2 R50.1 R54.2 U6.2 | length 399.6
  Top Layer w15: R54.2@3010,2768.5 3010,2700 C39.1@3020,2690 ; U6.2@3025,2519.57 3025,2598.5 R50.1@3018.5,2605 3018.5,2688.5 C39.1@3020,2690 ; D1.1@3119.09,2690.08 3119.02,2690 v2(3075,2690) C39.1@3020,2690
  Bottom Layer w15: v2(3075,2690) 3075.08,2690.08 D2.2@3119.09,2690.08
NetC39_2: C39.2 D3.2 D4.1 R180.1 R184.1 U6.3 | length 517.6
  Top Layer w15: R180.1@2808.5,2770 2808.5,2746.5 2835.59,2719.41 D4.1@2835.59,2681.5 2853.58,2681.5 2862.09,2690 v2(2885,2690) C39.2@2940,2690 ; C39.2@2945,2695 C39.2@2940,2690 ; U6.3@2975,2519.57 2975,2605 2940,2640 C39.2@2940,2690
  Top Layer w20: R180.1@2808.5,2770 R184.1@2808.5,2835
  Bottom Layer w15: D3.2@2835.59,2681.5 2853.58,2681.5 2862.09,2690 v2(2885,2690)
NetC44_1: C44.1 D5.1 D6.2 R64.2 R65.1 U7.2 | length 404.4
  Top Layer w15: R64.2@1780,2778.5 1780,2705 C44.1@1790,2695 ; U7.2@1790,2519.57 1790,2608.5 R65.1@1788.5,2610 1788.5,2693.5 C44.1@1790,2695 ; D5.1@1889.41,2693.5 1851.49,2693.5 v2(1850,2695) C44.1@1790,2695
  Bottom Layer w15: v2(1850,2695) 1887.91,2695 D6.2@1889.41,2693.5
NetC44_2: C44.2 D7.2 D8.1 R181.1 R185.1 U7.3 | length 525.5
  Top Layer w15: R181.1@1578.5,2780 1578.5,2751.5 1605.59,2724.41 D8.1@1605.59,2686.5 1628.58,2686.5 1637.09,2695 v2(1655,2695) C44.2@1710,2695 ; C44.2@1715,2700 C44.2@1710,2695 ; U7.3@1740,2519.57 1740,2620 1710,2650 C44.2@1710,2695
  Top Layer w20: R181.1@1578.5,2780 R185.1@1578.5,2845
  Bottom Layer w15: D7.2@1605.59,2686.5 1628.58,2686.5 1637.09,2695 v2(1655,2695)
NetC45_2: C45.2 C46.2 R182.1 T1.2 U9.2 | length 579.4
  Top Layer w20: v1(2310,2020) 2310,2055 2332.36,2077.36 T1.2@2370,2077.36 ; U9.2@2370,1944.13 2370,1975 v1(2385,1990) 2440,1990 2455,1975 2455,1946.5 C46.2@2480,1921.5 2505.59,1947.09 C45.2@2586,1947.09 2586,2022.5 R182.1@2588.5,2025
  Bottom Layer w20: v1(2310,2020) 2340,1990 v1(2385,1990)
NetC47_2: C47.2 C48.1 L3.2 R72.1 TP9.1 | length 334.5
  Top Layer w20: C47.2@2395,3323.5 C47.2@2403.5,3315
  Top Layer w25: C47.2@2395,3323.5 C48.1@2395,3405 ; R72.1@2395,3475 C48.1@2395,3405 ; C47.2@2403.5,3315 L3.2@2480.94,3315 ; TP9.1@2488.5,3405 C48.1@2395,3405
NetC49_2: C49.2 L3.1 U8.3 | length 212.9
  Top Layer w20: C49.2@2536.06,3234.53 C49.2@2538.5,3232.09
  Top Layer w25: U8.3@2417.64,3212.4 2450.91,3212.4 2470.59,3232.09 C49.2@2538.5,3232.09 ; C49.2@2536.06,3234.53 L3.1@2536.06,3315
NetC54_1: C54.1 R75.2 R79.1 U10.9 | length 407.1
  Top Layer w15: v1(3828.23,2488.29) C54.1@3871.73,2488.29 3915.21,2488.29 3923.49,2496.56 U10.9@3968.18,2496.56 4003.49,2496.56 4020,2513.07 4020,2560 4000,2580 3975,2580 3961,2594 R79.1@3961,2635.5
  Bottom Layer w15: v1(3828.23,2488.29) 3828.45,2488.07 R75.2@3871.73,2488.07
NetC54_2: C54.2 R75.1 R81.1 TP11.1 U10.8 | length 289.9
  Top Layer w15: TP11.1@3782.3,2609.78 R81.1@3782.3,2551.28 3828.01,2551.28 v1(3828.23,2551.06) C54.2@3871.73,2551.06 ; C54.2@3871.73,2551.28 3911.79,2551.28 3916.51,2546.56 U10.8@3968.18,2546.56
  Bottom Layer w15: v1(3828.23,2551.06) R75.1@3871.73,2551.06
NetC55_1: C55.1 R77.2 R82.1 U11.9 | length 406.8
  Top Layer w15: v1(486.5,2628.5) C55.1@530,2628.5 568.5,2628.5 573.03,2633.03 U11.9@623.88,2633.03 663.03,2633.03 675,2645 675,2695 650,2720 625,2720 615,2730 R82.1@615,2773.5
  Bottom Layer w15: v1(486.5,2628.5) R77.2@530,2628.5
NetC55_2: C55.2 R77.1 R83.1 TP12.1 U11.8 | length 289.4
  Top Layer w15: R83.1@440,2691.5 v1(486.5,2691.5) C55.2@530,2691.5 563.5,2691.5 571.97,2683.03 U11.8@623.88,2683.03
  Bottom Layer w15: v1(486.5,2691.5) R77.1@530,2691.5 TP12.1@530,2750
NetC60_2: C60.2 D23.1 R84.1 R85.2 R88.2 R89.2 | length 1080.4
  Top Layer w15: C60.2@3722.68,3066.07 3722.68,3039.38 3740.4,3021.66 D23.1@3740.4,2991.07 3740.4,2814.6 3815,2740 4012,2740 4030,2722 R85.2@4030,2696.5 ; R88.2@3722.68,3206.07 3724.52,3207.91 R84.1@4050,3207.91
  Top Layer w20: C60.2@3722.68,3066.07 R89.2@3722.68,3136.07 R88.2@3722.68,3206.07
NetC61_2: C61.2 D24.1 R86.2 R87.1 R90.2 R91.2 | length 453.9
  Top Layer w15: R86.2@685,2836.5 685,2885 710.56,2910.56 D24.1@710.56,2934.86 710.56,2960.45 691.87,2979.14 C61.2@691.87,3004.39
  Top Layer w20: R87.1@662.46,3259.39 662.46,3212.54 692.46,3182.54 692.46,3144.98 R90.2@691.87,3144.39 R91.2@691.87,3074.39 C61.2@691.87,3004.39
NetC62_1: C62.1 R92.2 R95.1 U11.2 | length 388.1
  Top Layer w15: R95.1@835,2286.5 835,2315 790,2360 790,2420 803.03,2433.03 U11.2@838.45,2433.03 878.03,2433.03 886.5,2441.5 C62.1@930,2441.5 v1(973.5,2441.5)
  Bottom Layer w15: R92.2@930,2441.5 v1(973.5,2441.5)
NetC62_2: C62.2 R92.1 R97.1 TP16.1 U11.1 | length 280.4
  Top Layer w15: U11.1@838.45,2383.03 881.97,2383.03 886.5,2378.5 C62.2@930,2378.5 v1(973.5,2378.5) R97.1@1020,2378.5 TP16.1@1020,2325
  Bottom Layer w15: R92.1@930,2378.5 v1(973.5,2378.5)
NetC63_1: C63.1 R93.2 R94.1 U10.2 | length 391.1
  Top Layer w15: R94.1@4175,2154.57 4175,2190 4130,2235 4130,2283.07 4143.49,2296.56 U10.2@4182.75,2296.56 4223.49,2296.56 4233.21,2306.28 C63.1@4277.3,2306.28 v1(4320.8,2306.28)
  Bottom Layer w15: R93.2@4277.3,2306.28 v1(4320.8,2306.28)
NetC63_2: C63.2 R93.1 R96.1 TP15.1 U10.1 | length 285.4
  Top Layer w15: U10.1@4182.75,2246.56 4226.51,2246.56 4229.79,2243.29 C63.2@4277.3,2243.29 v1(4320,2243.29) R96.1@4366.41,2243.29 TP15.1@4366.41,2185.57
  Bottom Layer w15: R93.1@4277.3,2243.29 v1(4320,2243.29)
NetC65_1: C65.1 C122.1 D25.1 J7.2 R94.2 R100.2 R101.2 R141.1 TP13.1 | length 1259.5
  Top Layer w15: v1(4000,1635) 4000,1660 3990.79,1669.21 D25.1@3955,1669.21 3955,1751.95 3978.05,1775 4105,1775 4175,1845 R94.2@4175,2091.58
  Top Layer w20: v1(4000,1635) C122.1@4055,1635 4126.5,1635 R101.2@4135,1626.5 ; TP13.1@4140,1750 4138.5,1748.5 R141.1@4138.5,1700 4135,1696.5 R101.2@4135,1626.5 ; J7.2@4403,1650 4305,1650 4281.5,1626.5 R100.2@4205,1626.5 R101.2@4135,1626.5
  Bottom Layer w20: v1(4000,1635) 4052.5,1635 C65.1@4055,1632.5
NetC65_2: C65.2 C124.2 D25.2 J7.1 R98.2 R100.1 R101.1 | length 1264.4
  Top Layer w15: v1(4000.5,1569.5) 3956.28,1569.5 D25.2@3955,1570.79 3929.41,1570.79 3910,1590.2 3910,1765 3950,1805 4090,1805 4140,1855 4140,2020 4105,2055 R98.2@4105,2091.58
  Top Layer w20: v1(4000.5,1569.5) 4015,1555 C124.2@4055,1555 4063.5,1563.5 R101.1@4135,1563.5 R100.1@4205,1563.5 4296.5,1563.5 4310,1550 J7.1@4403,1550
  Bottom Layer w20: v1(4000.5,1569.5) C65.2@4055,1569.5
NetC66_1: C66.1 C123.1 D26.1 J8.2 R95.2 R102.2 R103.2 R142.1 TP14.1 | length 1118.5
  Top Layer w15: C123.1@510,1900 583.53,1900 C66.1@591.07,1907.54 ; TP14.1@591.07,1844.04 C66.1@591.07,1907.54 ; R95.2@835,2223.5 835,2120 720,2005 720,1910 699.82,1889.82 D26.1@661.07,1889.82 635.28,1889.82 617.57,1907.54 C66.1@591.07,1907.54
  Top Layer w20: J8.2@155,1895 262.48,1895 281.96,1914.48 R102.2@355.14,1914.48 R103.2@425.14,1914.48 ; R142.1@421.5,1820 425.14,1823.64 R103.2@425.14,1914.48 ; C123.1@510,1900 470,1900 455.52,1914.48 R103.2@425.14,1914.48
NetC66_2: C66.2 C125.2 D26.2 J8.1 R99.2 R102.1 R103.1 | length 829.4
  Top Layer w15: C66.2@591.07,1970.53 620.53,1970.53 638.25,1988.25 D26.2@661.07,1988.25 683.25,1988.25 697,2002 697,2022 780,2105 780,2170 765,2185 R99.2@765,2223.5
  Top Layer w20: J8.1@155,1995 254.61,1995 272.13,1977.48 R102.1@355.14,1977.48 R103.1@425.14,1977.48 427.66,1980 C125.2@510,1980 519.47,1970.53 C66.2@591.07,1970.53
NetC70_1: C70.1 R104.2 R110.1 U10.6 | length 390.9
  Top Layer w15: R110.1@4180,2633.5 4180,2595 4165,2580 4150,2580 4135,2565 4135,2507.08 4145.52,2496.56 U10.6@4182.75,2496.56 4220.52,2496.56 4228.8,2488.29 C70.1@4277.3,2488.29 v1(4320.8,2488.29)
  Bottom Layer w15: R104.2@4277.3,2488.29 v1(4320.8,2488.29)
NetC70_2: C70.2 R104.1 R111.1 TP19.1 U10.7 | length 288.9
  Top Layer w15: U10.7@4182.75,2546.56 4229.08,2546.56 4233.8,2551.28 C70.2@4277.3,2551.28 v1(4320.8,2551.28) ; v1@4321.02,2551.5 R111.1@4367.87,2551.5 TP19.1@4367.87,2610
  Bottom Layer w15: R104.1@4277.3,2551.28 v1(4320.8,2551.28)
NetC71_1: C71.1 R105.2 R112.1 U11.6 | length 396.8
  Top Layer w15: R112.1@845,2773.5 845,2735 830,2720 810,2720 790,2700 790,2645 801.97,2633.03 U11.6@838.45,2633.03 881.97,2633.03 886.5,2628.5 C71.1@930,2628.5 v1(973.5,2628.5)
  Bottom Layer w15: R105.2@930,2628.5 v1(973.5,2628.5)
NetC71_2: C71.2 R105.1 R113.1 TP20.1 U11.7 | length 283.4
  Top Layer w15: U11.7@838.45,2683.03 883.03,2683.03 891.5,2691.5 C71.2@930,2691.5 v1(973.5,2691.5) R113.1@1021.32,2691.5 TP20.1@1021.32,2745
  Bottom Layer w15: R105.1@930,2691.5 v1(973.5,2691.5)
NetC72_1: C72.1 C127.1 D27.1 J9.2 R106.2 R107.2 R112.2 R171.1 TP17.1 | length 969.9
  Top Layer w15: R112.2@845,2836.5 845,2905 905.79,2965.79 D27.1@905.79,3108.19 905.79,3133.78 923.5,3151.49 C72.1@923.5,3178.19
  Top Layer w20: R171.1@830,3343.5 835.32,3338.19 R107.2@923.5,3338.19 ; TP17.1@869.41,3178.19 C72.1@923.5,3178.19 923.5,3202.95 914,3212.45 C127.1@914,3260 914,3300 923.5,3309.5 R107.2@923.5,3338.19 ; J9.2@905,3608.58 905,3508.97 923.5,3490.47 R106.2@923.5,3408.19 R107.2@923.5,3338.19
NetC72_2: C72.2 C129.2 D27.2 J9.1 R106.1 R107.1 R115.2 | length 919.1
  Top Layer w15: R115.2@775,2836.5 v1(775,2880) ; C72.2@986.5,3178.19 986.5,3148.5 1004.21,3130.79 D27.2@1004.21,3108.19 v1(1004.21,3065.79)
  Top Layer w20: C72.2@986.5,3178.19 986.5,3202.95 999,3215.45 C129.2@999,3260 999,3300 986.5,3312.5 R107.1@986.5,3338.19 R106.1@986.5,3408.19 986.5,3491.77 1005,3510.27 J9.1@1005,3609.88
  Bottom Layer w15: v1(775,2880) 960.79,3065.79 v1(1004.21,3065.79)
NetC73_1: C73.1 C126.1 D28.1 J10.2 R108.2 R109.2 R110.2 R170.1 TP18.1 | length 1184.3
  Top Layer w15: v1(3865,2955) 3884.21,2974.21 D28.1@3915,2974.21 3930.79,2974.21 3948.5,2956.5 C73.1@3980,2956.5 TP18.1@3980,3020 ; R110.2@4180,2696.5 v1(4180,2755)
  Top Layer w20: C73.1@3980,2956.5 4006.5,2956.5 4021,2971 C126.1@4060,2971 4100,2971 4113.5,2957.5 R109.2@4140,2957.5 ; R170.1@4143.5,3055 4140,3051.5 R109.2@4140,2957.5 ; J10.2@4396.3,2974.99 4296.69,2974.99 4279.19,2957.5 R108.2@4205,2957.5 R109.2@4140,2957.5
  Bottom Layer w15: v1(3865,2955) 4065,2755 v1(4180,2755)
NetC73_2: C73.2 C128.2 D28.2 J10.1 R108.1 R109.1 R114.2 | length 826.6
  Top Layer w15: C73.2@3980,2893.5 3948.5,2893.5 3930.79,2875.79 D28.2@3915,2875.79 3915,2815 3965,2765 4080,2765 4110,2735 R114.2@4110,2696.5
  Top Layer w20: C73.2@3980,2893.5 3982.5,2891 C128.2@4060,2891 4063.5,2894.5 R109.1@4140,2894.5 R108.1@4205,2894.5 4277.18,2894.5 4296.69,2874.99 J10.1@4396.3,2874.99
NetC78_2: C78.2 C79.1 L4.2 R134.1 TP23.1 | length 366.3
  Top Layer w20: C78.2@840,355 842.56,352.44 L4.2@920,352.44 947.44,352.44 1000,405 TP23.1@1000,410 ; C78.2@840,370 C78.2@840,375
  Top Layer w25: C78.2@840,370 840,355 840,288.5 C79.1@836.5,285 R134.1@923.5,285
NetC80_2: C80.2 L4.1 U14.3 | length 112.3
  Top Layer w20: C80.2@872.09,500 872.09,477.91 920,430 L4.1@920,407.56
NetC89_1: C89.1 U15.4 | length 79.7
  Top Layer w15: U15.4@430.59,1194.29 450.71,1194.29 463.5,1181.5 C89.1@505,1181.5
NetC92_1: C92.1 U16.4 | length 79.7
  Top Layer w15: U16.4@150.59,1194.29 175.71,1194.29 188.5,1181.5 C92.1@225,1181.5
NetC93_1: C93.1 U17.5 | length 263.2
  Top Layer w15: C93.1@851.5,1065 885,1065 900,1050 900,890 885.87,875.87 U17.5@857.4,875.87
NetC93_2: C93.2 U17.3 | length 83.3
  Top Layer w15: U17.3@782.6,984.13 782.6,1022.6 788.5,1028.5 C93.2@788.5,1065
NetC94_1: C94.1 C95.1 U17.1 U18.2 U18.3 | length 373
  Top Layer w15: U17.1@857.4,984.13 857.4,942.4 825,910 825,845 861.5,808.5 C94.1@861.5,800 C95.1@978.5,800 ; 1000,675 1010,685 U18.2@1010,714.13
NetC96_1: C96.1 C97.1 D20.1 U17.2 | length 330.9
  Top Layer w15: C97.1@710,961.5 743.5,961.5 760,945 810,945 820,955 U17.2@820,984.13
  Top Layer w25: D20.1@530,959.47 632.97,959.47 C96.1@635,961.5 C97.1@710,961.5
NetC100_1: C100.1 U18.4 | length 88.3
  Top Layer w20: U18.4@972.6,605.87 972.6,567.4 978.5,561.5 C100.1@978.5,520
NetC102_1: C102.1 R136.2 U2.1 | length 357.6
  Top Layer w8: U2.1@3338.96,1355.33 3338.96,1393.9 3390.07,1445 C102.1@3390.07,1473.5 3418.5,1473.5 3430.07,1485.07 3430.07,1614.93 3421.5,1623.5 R136.2@3390.07,1623.5
NetC103_1: C103.1 R137.2 U2.3 | length 324
  Top Layer w8: U2.3@3299.59,1355.33 3300.07,1355.8 C103.1@3300.07,1473.5 3323.5,1473.5 3332,1482 3332,1618 3326.5,1623.5 R137.2@3300.07,1623.5
NetC104_1: C104.1 R138.2 U2.5 | length 342.5
  Top Layer w8: R138.2@3215.07,1623.5 3241.5,1623.5 3247,1618 3247,1482 3238.5,1473.5 C104.1@3215.07,1473.5 3215.07,1445 3260.22,1399.84 U2.5@3260.22,1355.33
NetC107_1: C107.1 R158.2 U4.3 | length 329.5
  Top Layer w8: U4.3@2294.59,1355.33 2294.59,1473.03 C107.1@2295.07,1473.5 2323.5,1473.5 2330,1480 2330,1615 2321.5,1623.5 R158.2@2295.07,1623.5
NetC108_1: C108.1 R159.2 U4.5 | length 343.4
  Top Layer w8: R159.2@2210.07,1623.5 2236.5,1623.5 2243,1617 2243,1483 2233.5,1473.5 C108.1@2210.07,1473.5 2210.07,1441.93 2255.22,1396.78 U4.5@2255.22,1355.33
NetC109_1: C109.1 R160.2 U4.7 | length 384.9
  Top Layer w8: R160.2@2125.07,1623.5 2151.5,1623.5 2157,1618 2157,1482 2148.5,1473.5 C109.1@2125.07,1473.5 2125.07,1434.93 2160,1400 2200,1400 2215.85,1384.15 U4.7@2215.85,1355.33
NetC130_1: C130.1 R146.1 U1.4 | length 223.3
  Top Layer w8: R146.1@3880.13,1373.5 v1(3880.13,1325.13) 3870,1315 3870,1265 3885,1250 3925.53,1250 U1.4@3925.84,1249.68
  Bottom Layer w8: C130.1@3880,1373.5 3880,1325.26 v1(3880.13,1325.13)
NetC131_1: C131.1 R145.1 U1.5 | length 162.6
  Top Layer w8: U1.5@3925.84,1269.37 3925.84,1300.84 v1(3950.13,1325.13) R145.1@3950.13,1373.5
  Bottom Layer w8: C131.1@3950,1373.5 3950,1325.26 v1(3950.13,1325.13)
NetC132_1: C132.1 R144.1 U1.6 | length 162.9
  Top Layer w8: R144.1@3740.13,1373.5 v1(3740.13,1324.87) 3764.42,1300.58 U1.6@3764.42,1269.37
  Bottom Layer w8: C132.1@3740,1373.5 3740,1325 v1(3740.13,1324.87)
NetC133_1: C133.1 R143.1 U1.7 | length 229.6
  Top Layer w8: U1.7@3764.42,1249.68 3814.82,1249.68 3820.54,1255.41 3820.54,1314.46 v1(3810.13,1324.87) R143.1@3810.13,1373.5
  Bottom Layer w8: C133.1@3810,1373.5 3810,1325 v1(3810.13,1324.87)
NetC134_1: C134.1 R150.1 U3.4 | length 228.2
  Top Layer w8: R150.1@1255.07,1373.5 v1(1255.07,1320.07) 1245,1310 1245,1265 1260,1250 1300.46,1250 U3.4@1300.77,1249.68
  Bottom Layer w8: v1@1255,1320.13 C134.1@1255,1373.5
NetC135_1: C135.1 R149.1 U3.5 | length 162.7
  Top Layer w8: U3.5@1300.77,1269.37 1300.77,1300.77 v1(1325.07,1325.07) R149.1@1325.07,1373.5
  Bottom Layer w8: C135.1@1325,1373.5 1325,1325.13 v1(1325.07,1325.07)
NetC136_1: C136.1 R148.1 U3.6 | length 162.8
  Top Layer w8: R148.1@1115.07,1373.5 v1(1115.07,1324.93) 1139.36,1300.64 U3.6@1139.36,1269.37
  Bottom Layer w8: C136.1@1115,1373.5 1115,1325 v1(1115.07,1324.93)
NetC137_1: C137.1 R147.1 U3.7 | length 228.2
  Top Layer w8: U3.7@1139.36,1249.68 1179.68,1249.68 1195,1265 1195,1310 v1(1185.07,1319.93) R147.1@1185.07,1373.5
  Bottom Layer w8: C137.1@1185,1373.5 1185,1320 v1(1185.07,1319.93)
NetD9_2: D9.2 T1.6 | length 143
  Top Layer w25: D9.2@2213.5,2650.53 2213.5,2611.5 2249.92,2575.08 T1.6@2249.92,2522.64
NetD11_2: D11.2 R73.1 | length 71
  Top Layer w20: R73.1@2360,3665 D11.2@2431.02,3665
NetD12_2: D12.2 T1.4 | length 141.7
  Top Layer w25: T1.4@2490.08,2522.64 2490.08,2580.08 2523.5,2613.5 D12.2@2523.5,2650.53
NetD13_1: D13.1 R122.1 R132.2 U12.3 | length 348.3
  Top Layer w15: R122.1@3465,1788.5 3511.5,1788.5 3526.5,1773.5 3583.5,1773.5 3607.4,1797.4 D13.1@3607.4,1822.24 3680.51,1822.24 U12.3@3680.87,1822.6 3680.87,1751.22 R132.2@3695,1737.09
NetD14_1: D14.1 R123.1 R133.2 U21.3 | length 369.1
  Top Layer w15: R123.1@839.13,1911.55 844.63,1917.05 974.13,1917.05 986.54,1929.45 D14.1@986.54,1959.29 986.89,1959.65 U21.3@1075,1959.65 1075,1865 R133.2@1074.13,1864.13
NetD16_2: D16.2 R135.1 | length 76
  Top Layer w20: D16.2@802.48,100 R135.1@878.5,100
NetD21_1: D21.1 R53.2 R54.1 R55.2 R56.2 | length 342.8
  Top Layer w15: R54.1@3010,2831.5 3010,2870 3029.21,2889.21 D21.1@3029.21,2920 3029.21,2944.61 3012.46,2961.36 R56.2@3012.46,2996.07
  Top Layer w20: R56.2@3012.46,2996.07 R55.2@3012.46,3061.07 3014.3,3062.91 R53.2@3110,3062.91
NetD21_2: D21.2 R55.1 R56.1 R59.2 R60.1 | length 324.4
  Top Layer w15: R60.1@2943.5,2830 R60.1@2945,2831.5 2945,2870 2930.79,2884.21 D21.2@2930.79,2920 2930.79,2945.59 2949.47,2964.27 R56.1@2949.47,2996.07
  Top Layer w20: R59.2@2875,3050 2886.07,3061.07 R55.1@2949.47,3061.07 R56.1@2949.47,2996.07
NetD22_1: D22.1 R63.2 R64.1 R67.2 R68.2 | length 329.6
  Top Layer w15: R64.1@1780,2841.5 1780,2880 1804.21,2904.21 D22.1@1804.21,2921.02 1804.21,2945.63 1791.5,2958.35 R68.2@1791.5,2996.02
  Top Layer w20: R68.2@1791.5,2996.02 R67.2@1791.5,3061.02 1794.61,3057.91 R63.2@1885,3057.91
NetD22_2: D22.2 R67.1 R68.1 R70.2 R71.1 | length 315.8
  Top Layer w15: R71.1@1715,2841.5 1715,2885 1705.79,2894.21 D22.2@1705.79,2921.02 1705.79,2946.61 1728.5,2969.33 R68.1@1728.5,2996.02
  Top Layer w20: R70.2@1650,3050 1661.02,3061.02 R67.1@1728.5,3061.02 R68.1@1728.5,2996.02
NetJ3_1: J3.1 R51.1 | length 187.1
  Top Layer w20: J3.1@2925.96,3580 2943.05,3597.09 R51.1@3105.96,3597.09
NetJ4_1: J4.1 R61.1 | length 196.2
  Top Layer w20: J4.1@1700,3580 1717.09,3597.09 R61.1@1885,3597.09 ; J4.1@1700,3600 J4.1@1702.91,3597.09
NetJ5_1: J5.1 R74.2 | length 192.2
  Top Layer w20: J5.1@3770.47,3580 3767.01,3583.47 3818.54,3635 R74.2@3932.91,3635
NetJ6_1: J6.1 R76.2 | length 219
  Top Layer w20: R76.2@129.17,3258.51 R76.2@128.29,3259.39 128.29,3151.71 159.17,3120.83 J6.1@159.17,3054.39
NetJ11_2: J11.2 J12.1 | length 457.4
  Top Layer w20: J11.2@210,1640 210,1559 240,1529 451,1529 480,1558 J12.1@480,1640
NetR1_1: R1.1 U1.8 | length 227
  Top Layer w8: U1.8@3764.42,1230 3825.13,1230 3855.13,1200 3855.13,1149.87 3880.07,1124.93 R1.1@3880.07,1086.5
NetR2_2: R2.2 U1.9 | length 192.1
  Top Layer w8: U1.9@3764.42,1210.31 3813.32,1210.31 3835.13,1188.5 3835.13,1150.13 3810.13,1125.13 R2.2@3810.13,1086.49
NetR3_1: R3.1 U1.10 | length 114.2
  Top Layer w8: R3.1@3740.07,1086.5 3740.07,1129.93 3764.42,1154.29 U1.10@3764.42,1190.63
NetR4_1: R4.1 U1.1 | length 114.2
  Top Layer w8: U1.1@3925.84,1190.63 3925.84,1149.29 3950.07,1125.06 R4.1@3950.07,1086.5
NetR5_1: R5.1 R9.2 U2.30 | length 226.3
  Top Layer w8: U2.30@3396.05,1258.87 3456.19,1258.87 v1(3505.07,1210) R5.1@3553.57,1210
  Bottom Layer w8: v1(3505.07,1210) R9.2@3553.57,1210
NetR6_1: R6.1 R10.2 U2.31 | length 214.9
  Top Layer w8: U2.31@3396.05,1278.56 3483.62,1278.56 v1(3505.07,1300) R6.1@3553.57,1300
  Bottom Layer w8: v1(3505.07,1300) R10.2@3553.57,1300
NetR7_1: R7.1 R11.2 U2.32 | length 258.7
  Top Layer w8: U2.32@3396.05,1298.24 3438.31,1298.24 3505.07,1365 v1(3505.07,1390) R7.1@3553.57,1390
  Bottom Layer w8: v1(3505.07,1390) R11.2@3553.57,1390
NetR8_2: R8.2 TP2.1 U2.16 | length 183.5
  Top Layer w8: TP2.1@3055.07,1035 3055.07,1046.49 3090.07,1081.49 R8.2@3125.07,1081.49 3125.07,1110 3144.08,1129.02 U2.16@3144.08,1160.44 U2.16@3143.64,1160
NetR14_2: R14.2 U2.17 | length 249.3
  Top Layer w8: R14.2@3090.07,926.49 3090.07,955.07 3110,975 3155.07,975 3201.17,1021.1 U2.17@3201.17,1103.36
NetR15_2: R15.2 U2.23 | length 265
  Top Layer w8: U2.23@3319.28,1103.36 3319.28,1010.72 3335,995 3400,995 3440.07,954.93 R15.2@3440.07,926.49
NetR16_2: R16.2 U2.22 | length 223.6
  Top Layer w8: U2.22@3299.59,1103.36 3299.59,1000.41 3327.5,972.5 3357.5,972.5 3370.07,959.93 R16.2@3370.07,926.49
NetR17_2: R17.2 U2.20 | length 189.4
  Top Layer w8: R17.2@3230.07,926.49 3230.07,965.07 3260.22,995.22 U2.20@3260.22,1103.36
NetR18_2: R18.2 U2.21 | length 185.2
  Top Layer w8: U2.21@3279.91,1103.36 3279.91,995.09 3300.07,974.93 R18.2@3300.07,926.49
NetR19_2: R19.2 U2.19 | length 225.7
  Top Layer w8: R19.2@3160.07,926.49 3186.49,926.49 3195,935 3195,960 3240.54,1005.54 U2.19@3240.54,1103.36
NetR20_2: R20.2 R116.2 R126.1 U10.14 | length 267.7
  Top Layer w15: R20.2@3860,2128.07 3920,2128.07 3925,2123.07 3960,2123.07 ; U10.14@3968.18,2246.56 3968.18,2158.39 R116.2@3968.5,2158.07 3968.5,2131.58 3960,2123.07 ; R126.1@3968.5,2088.07 3968.5,2112.77 3960,2121.27 3960,2123.07
NetR21_1: R21.1 U2.25 | length 219.3
  Top Layer w8: U2.25@3396.05,1160.44 3396.05,1118.95 3445,1070 R21.1@3553.57,1070
NetR22_1: R22.1 R23.2 | length 3582.8
  Top Layer w15: R23.2@370,2205 370,2165 390,2145 v1(455,2145)
  Top Layer w20: v1(3685,2048.07) R22.1@3750,2048.07
  Bottom Layer w15: v1(455,2145) 670,2145 890,1925 2875,1925 2960,2010 3200,2010 3215,1995 3399.5,1995 3452.57,2048.07 v1(3685,2048.07)
NetR22_2: R22.2 R151.2 R153.2 U10.12 | length 567.4
  Top Layer w15: R153.2@3738.62,2308.07 R151.2@3860,2308.07 3905.59,2308.07 ; R22.2@3750,2128.07 3755.59,2128.07 3807.3,2179.78 3902.3,2179.78 3917.3,2194.78 3917.3,2294.78 3905.59,2306.49 3905.59,2308.07 ; U10.12@3968.18,2346.56 3929.08,2346.56 3917.3,2334.78 3917.3,2319.78 3905.59,2308.07
NetR23_1: R23.1 R154.2 R156.2 U11.12 | length 612.7
  Top Layer w15: R23.1@370,2285 370,2320 383,2333 538,2333 560,2355 560,2445 545,2460 ; R156.2@371.46,2460 R154.2@490,2460 545,2460 ; U11.12@623.88,2483.03 568.03,2483.03 545,2460
NetR24_1: R24.1 U3.8 | length 227
  Top Layer w8: U3.8@1139.36,1230 1200.07,1230 1230.07,1200 1230.07,1144.93 1255,1120 R24.1@1255,1086.5
NetR25_2: R25.2 U3.9 | length 192.1
  Top Layer w8: U3.9@1139.36,1210.31 1188.26,1210.31 1210.07,1188.5 1210.07,1150.07 1185.07,1125.07 R25.2@1185.07,1086.5
NetR26_1: R26.1 U3.10 | length 114.2
  Top Layer w8: R26.1@1115,1086.5 1115,1129.93 1139.36,1154.29 U3.10@1139.36,1190.63
NetR27_1: R27.1 U3.1 | length 114.2
  Top Layer w8: U3.1@1300.77,1190.63 1300.77,1149.29 1325,1125.07 R27.1@1325,1086.5
NetR28_1: R28.1 R32.2 U4.30 | length 226.3
  Top Layer w8: U4.30@2391.05,1258.87 2451.19,1258.87 v1(2500.07,1210) R28.1@2548.57,1210
  Bottom Layer w8: v1(2500.07,1210) R32.2@2548.57,1210
NetR29_1: R29.1 R33.2 U4.31 | length 214.9
  Top Layer w8: U4.31@2391.05,1278.56 2478.62,1278.56 v1(2500.07,1300) R29.1@2548.57,1300
  Bottom Layer w8: v1(2500.07,1300) R33.2@2548.57,1300
NetR30_1: R30.1 R34.2 U4.32 | length 258.7
  Top Layer w8: U4.32@2391.05,1298.24 2433.31,1298.24 2500.07,1365 v1(2500.07,1390) R30.1@2548.57,1390
  Bottom Layer w8: v1(2500.07,1390) R34.2@2548.57,1390
NetR31_2: R31.2 TP7.1 U4.16 | length 183.5
  Top Layer w8: TP7.1@2050.07,1035 2050.07,1046.49 2085.07,1081.49 R31.2@2120.07,1081.49 2120.07,1110 2139.08,1129.02 U4.16@2139.08,1160.44 U4.16@2138.64,1160
NetR37_2: R37.2 U4.17 | length 252.2
  Top Layer w8: R37.2@2085.07,926.49 2085.07,960.07 2100,975 2150.07,975 2196.17,1021.1 U4.17@2196.17,1103.36
NetR38_2: R38.2 TP24.1 U4.23 | length 365.4
  Top Layer w8: U4.23@2314.28,1103.36 2314.28,1055.79 2355.06,1015 2416.56,1015 R38.2@2505.07,926.49 TP24.1@2505.07,1000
